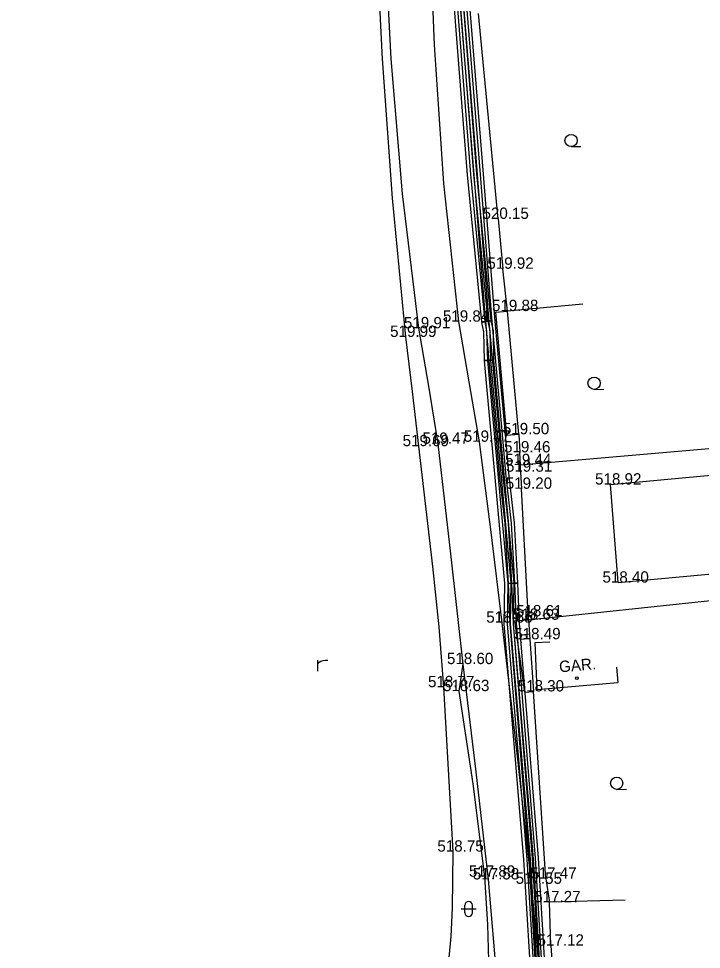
# Model space of a CAD drawing. Extents: x -669642 to -669119, y -1131006 to -1130466.
# Drawn here: x -669490.6 to -669445.4, y -1130940.6 to -1130879 of the extents above; entities that cross this region are included whole.
import ezdxf

# ---------------------------------------------------------------- set-up
doc = ezdxf.new("R2010")
doc.units = 0
for name, color, linetype in [('G_Bod_tecka', 7, 'Continuous'), ('G_Bod_vyska', 7, 'Continuous'), ('G_Breh_Teren', 7, 'Continuous'), ('G_Budovy-znacky', 7, 'Continuous'), ('G_Budovy_Objekty', 7, 'Continuous'), ('G_Plochy_zpevnene', 7, 'Continuous'), ('G_Ploty', 7, 'Continuous'), ('G_Ploty_vstupy', 7, 'Continuous'), ('G_Popisy_objektu', 7, 'Continuous'), ('G_Popisy_povrchu', 7, 'Continuous'), ('G_Site-Sloupy', 7, 'Continuous'), ('G_Z_CHRANICKA-TEPLOVOD_kotovane', 7, 'Continuous'), ('G_Z_ELsilove_podz_kotovane', 7, 'Continuous'), ('G_Z_SPOJE_podz_kotovane', 7, 'Continuous'), ('G_Zelen-Znacky', 7, 'Continuous')]:
    doc.layers.add(name, color=color, linetype=linetype)

msp = doc.modelspace()

# ---------------------------------------------------------------- linework, layer by layer
at = {"layer": 'G_Bod_tecka'}
for p, q in [((-669458.84, -1130892.24), (-669458.84, -1130892.24)), ((-669458.54, -1130895.54), (-669458.54, -1130895.54)), ((-669458.23, -1130898.34), (-669458.23, -1130898.34)), ((-669461.48, -1130899.04), (-669461.48, -1130899.04)), ((-669464.12, -1130899.48), (-669464.12, -1130899.48)), ((-669464.97, -1130900.05), (-669464.97, -1130900.05)), ((-669457.49, -1130906.49), (-669457.49, -1130906.49)), ((-669464.13, -1130907.28), (-669464.13, -1130907.28)), ((-669462.83, -1130907.12), (-669462.83, -1130907.12)), ((-669460.1, -1130906.99), (-669460.1, -1130906.99)), ((-669457.42, -1130907.69), (-669457.42, -1130907.69)), ((-669457.37, -1130908.53), (-669457.37, -1130908.53)), ((-669457.37, -1130908.97), (-669457.37, -1130908.97)), ((-669451.41, -1130909.82), (-669451.41, -1130909.82)), ((-669457.3, -1130910.1), (-669457.3, -1130910.1)), ((-669450.9, -1130916.31), (-669450.9, -1130916.31)), ((-669458.6, -1130918.96), (-669458.6, -1130918.96)), ((-669456.83, -1130918.77), (-669456.83, -1130918.77)), ((-669456.69, -1130918.54), (-669456.69, -1130918.54)), ((-669456.76, -1130920.06), (-669456.76, -1130920.06)), ((-669461.18, -1130921.7), (-669461.18, -1130921.7)), ((-669462.47, -1130923.23), (-669462.47, -1130923.23)), ((-669461.46, -1130923.49), (-669461.46, -1130923.49)), ((-669456.51, -1130923.51), (-669456.51, -1130923.51)), ((-669461.85, -1130934.11), (-669461.85, -1130934.11)), ((-669459.76, -1130935.77), (-669459.76, -1130935.77)), ((-669459.5, -1130935.95), (-669459.5, -1130935.95)), ((-669456.67, -1130936.24), (-669456.67, -1130936.24)), ((-669455.7, -1130935.9), (-669455.7, -1130935.9)), ((-669455.44, -1130937.46), (-669455.44, -1130937.46)), ((-669455.36, -1130940.33), (-669455.36, -1130940.33))]:
    msp.add_line(p, q, dxfattribs=at)
at = {"layer": 'G_Breh_Teren'}
msp.add_line((-669461.18, -1130921.7), (-669461.46, -1130923.49), dxfattribs=at)
for points in [[(-669466.84, -1130875.5), (-669466.52, -1130881.65), (-669465.86, -1130890.86), (-669464.97, -1130900.05), (-669464.55, -1130903.67), (-669464.13, -1130907.28), (-669463.19, -1130915.25), (-669462.78, -1130919.23), (-669462.47, -1130923.23), (-669462.16, -1130928.67), (-669461.85, -1130934.11)], [(-669461.46, -1130923.49), (-669460.53, -1130929.62), (-669459.76, -1130935.77), (-669459.56, -1130938.93), (-669459.43, -1130943.69), (-669459.32, -1130948.45)], [(-669461.85, -1130934.11), (-669461.9, -1130937.86), (-669461.97, -1130939.73), (-669462.15, -1130941.58), (-669462.94, -1130945.65), (-669464.57, -1130951.69), (-669466.27, -1130957.72)]]:
    msp.add_lwpolyline(points, dxfattribs=at)
at = {"layer": 'G_Budovy-znacky'}
msp.add_circle((-669453.639, -1130922.63), 0.0875, dxfattribs=at)
at = {"layer": 'G_Budovy_Objekty'}
for p, q in [((-669450.9, -1130916.31), (-669443.02, -1130915.58)), ((-669455.42, -1130920.26), (-669456.42, -1130920.3)), ((-669456.42, -1130920.3), (-669456.28, -1130923.39)), ((-669451.02, -1130921.91), (-669450.93, -1130922.91)), ((-669456.28, -1130923.39), (-669450.93, -1130922.91))]:
    msp.add_line(p, q, dxfattribs=at)
for points in [[(-669451.41, -1130909.82), (-669435.52, -1130908.33)], [(-669450.9, -1130916.31), (-669451.41, -1130909.82)]]:
    msp.add_lwpolyline(points, dxfattribs=at)
at = {"layer": 'G_Plochy_zpevnene'}
for p, q in [((-669457.77, -1130918.84), (-669456.83, -1130918.77)), ((-669457.77, -1130918.84), (-669457.11, -1130923.55)), ((-669457.11, -1130923.55), (-669456.51, -1130923.51))]:
    msp.add_line(p, q, dxfattribs=at)
for points in [[(-669463.32, -1130874.6), (-669463.08, -1130880.72), (-669462.46, -1130889.89), (-669461.48, -1130899.04), (-669460.79, -1130903.02), (-669460.1, -1130906.99), (-669459.33, -1130912.97), (-669458.6, -1130918.96), (-669457.62, -1130927.6), (-669456.67, -1130936.24), (-669456.11, -1130942.25)], [(-669466.25, -1130875.67), (-669465.96, -1130881.64), (-669465.2, -1130890.57), (-669464.12, -1130899.48), (-669463.45, -1130903.3), (-669462.83, -1130907.12), (-669462, -1130914.41), (-669461.18, -1130921.7), (-669460.33, -1130928.82), (-669459.5, -1130935.95), (-669458.98, -1130942.17)]]:
    msp.add_lwpolyline(points, dxfattribs=at)
at = {"layer": 'G_Ploty'}
for p, q in [((-669458.84, -1130892.24), (-669460.15, -1130878.65)), ((-669458.23, -1130898.34), (-669458.54, -1130895.54)), ((-669453.25, -1130897.89), (-669458.23, -1130898.34)), ((-669459.03, -1130898.41), (-669458.23, -1130898.34)), ((-669459.03, -1130898.41), (-669458.29, -1130906.56)), ((-669457.49, -1130906.49), (-669458.23, -1130898.34)), ((-669458.29, -1130906.56), (-669457.49, -1130906.49)), ((-669457.37, -1130908.53), (-669457.42, -1130907.69)), ((-669457.37, -1130908.97), (-669457.37, -1130908.53)), ((-669456.83, -1130918.77), (-669457.3, -1130910.1)), ((-669455.7, -1130935.9), (-669456.51, -1130923.51)), ((-669450.44, -1130937.32), (-669455.44, -1130937.46)), ((-669455.36, -1130940.33), (-669455.44, -1130937.46))]:
    msp.add_line(p, q, dxfattribs=at)
for points in [[(-669443.11, -1130907.31), (-669457.37, -1130908.53)], [(-669456.83, -1130918.77), (-669444.37, -1130917.45)]]:
    msp.add_lwpolyline(points, dxfattribs=at)
at = {"layer": 'G_Ploty_vstupy'}
for p, q in [((-669458.84, -1130892.24), (-669458.54, -1130895.54)), ((-669457.49, -1130906.49), (-669457.42, -1130907.69)), ((-669457.37, -1130908.97), (-669457.3, -1130910.1)), ((-669456.83, -1130918.77), (-669456.76, -1130920.06)), ((-669456.76, -1130920.06), (-669456.51, -1130923.51)), ((-669455.7, -1130935.9), (-669455.44, -1130937.46)), ((-669455.36, -1130940.33), (-669455.28, -1130941.62))]:
    msp.add_line(p, q, dxfattribs=at)
at = {"layer": 'G_Site-Sloupy'}
for radius in [0.25, 0.05]:
    msp.add_circle((-669456.69, -1130918.54), radius, dxfattribs=at)
at = {"layer": 'G_Z_CHRANICKA-TEPLOVOD_kotovane'}
for points in [[(-669463.464, -1130850.336), (-669463.211, -1130850.314), (-669462.571, -1130857.807), (-669461.451, -1130874.328), (-669460.281, -1130889.264), (-669459.334, -1130898.98), (-669459.332, -1130899.001), (-669459.63, -1130899.03), (-669459.669, -1130899.034), (-669459.929, -1130899.059), (-669460.878, -1130889.322), (-669462.049, -1130874.372), (-669463.169, -1130857.853), (-669463.809, -1130850.366)], [(-669463.088, -1130850.242), (-669462.871, -1130850.225), (-669462.091, -1130859.855), (-669461.051, -1130874.307), (-669459.841, -1130889.276), (-669459.091, -1130898.765), (-669458.411, -1130906.243), (-669458.412, -1130906.243), (-669458.462, -1130906.248), (-669458.732, -1130906.272), (-669459.009, -1130906.297), (-669459.435, -1130901.609), (-669459.435, -1130901.608), (-669459.669, -1130899.038), (-669459.669, -1130899.034), (-669459.689, -1130898.815), (-669460.439, -1130889.324), (-669461.649, -1130874.353), (-669462.689, -1130859.903), (-669463.464, -1130850.336), (-669463.469, -1130850.278), (-669463.469, -1130850.273)], [(-669459.63, -1130899.03), (-669459.337, -1130898.966), (-669459.334, -1130898.98), (-669459.187, -1130899.645), (-669459.159, -1130901.604), (-669459.159, -1130901.605), (-669459.435, -1130901.609), (-669459.453, -1130901.609), (-669459.76, -1130901.614), (-669459.787, -1130899.715), (-669459.923, -1130899.094), (-669459.669, -1130899.038)], [(-669458.412, -1130906.243), (-669458.132, -1130909.269), (-669457.781, -1130912.355), (-669457.57, -1130916.334), (-669457.81, -1130916.347), (-669457.825, -1130916.348), (-669458.17, -1130916.366), (-669458.17, -1130916.366), (-669458.379, -1130912.405), (-669458.729, -1130909.324), (-669459.009, -1130906.298), (-669458.732, -1130906.272), (-669458.462, -1130906.248)], [(-669457.81, -1130916.347), (-669457.572, -1130916.337), (-669457.461, -1130918.982), (-669456.191, -1130934.519), (-669455.313, -1130949.251), (-669453.393, -1130954.785), (-669451.504, -1130957.211), (-669448.877, -1130962.675), (-669448.87, -1130962.69), (-669449.081, -1130962.792), (-669449.14, -1130962.82), (-669449.41, -1130962.95), (-669452.016, -1130957.529), (-669453.927, -1130955.075), (-669455.907, -1130949.369), (-669456.789, -1130934.561), (-669458.059, -1130919.007), (-669458.17, -1130916.366), (-669458.17, -1130916.362), (-669457.825, -1130916.348)]]:
    msp.add_lwpolyline(points, close=True, dxfattribs=at)
msp.add_lwpolyline([(-669456.247, -1130949.405), (-669457.139, -1130934.632), (-669458.45, -1130919.06), (-669458.41, -1130916.371), (-669459.759, -1130901.637), (-669459.453, -1130901.609), (-669459.435, -1130901.608), (-669459.161, -1130901.583), (-669459.159, -1130901.604), (-669459.159, -1130901.605), (-669458.732, -1130906.272), (-669458.732, -1130906.272), (-669457.81, -1130916.347), (-669457.81, -1130916.347), (-669457.81, -1130916.349), (-669457.85, -1130919.04), (-669456.541, -1130934.588), (-669455.653, -1130949.295)], dxfattribs=at)
at = {"layer": 'G_Z_ELsilove_podz_kotovane'}
for points in [[(-669461.85, -1130874.357), (-669460.68, -1130889.299), (-669459.729, -1130899.044), (-669459.61, -1130899.661), (-669459.56, -1130901.616), (-669458.21, -1130916.364), (-669458.25, -1130919.053), (-669456.94, -1130934.617), (-669456.049, -1130949.368), (-669454.16, -1130955.298), (-669452.214, -1130957.705), (-669449.377, -1130963.09), (-669447.433, -1130966.166), (-669443.781, -1130971.308), (-669440.42, -1130975.92), (-669437.644, -1130979.538), (-669430.572, -1130986.049), (-669425.783, -1130989.308), (-669418.897, -1130995.885), (-669414.413, -1130999.608), (-669413.159, -1131000.6)], [(-669461.65, -1130874.343), (-669460.48, -1130889.281), (-669459.531, -1130899.016), (-669459.41, -1130899.639), (-669459.36, -1130901.604), (-669458.01, -1130916.356), (-669458.05, -1130919.047), (-669456.74, -1130934.603), (-669455.851, -1130949.332), (-669453.98, -1130955.202), (-669452.046, -1130957.595), (-669449.203, -1130962.99), (-669447.267, -1130966.054), (-669443.619, -1130971.192), (-669440.26, -1130975.8), (-669437.496, -1130979.402), (-669430.448, -1130985.891), (-669425.657, -1130989.152), (-669418.763, -1130995.735), (-669414.287, -1130999.452), (-669412.836, -1131000.6)]]:
    msp.add_lwpolyline(points, dxfattribs=at)
at = {"layer": 'G_Z_SPOJE_podz_kotovane'}
for points in [[(-669496.072, -1130721.41), (-669487.697, -1130721.789), (-669481.224, -1130725.264), (-669474.834, -1130730.162), (-669473.468, -1130733.802), (-669473.27, -1130736.156), (-669472.44, -1130755.333), (-669472.33, -1130769.914), (-669471.45, -1130783.056), (-669470.88, -1130792.458), (-669469.649, -1130805.302), (-669467.579, -1130819.436), (-669465.879, -1130828.666), (-669464.319, -1130839.252), (-669463.27, -1130850.259), (-669462.68, -1130857.899), (-669462.49, -1130859.888), (-669461.45, -1130874.338), (-669460.24, -1130889.308), (-669459.49, -1130898.798), (-669458.81, -1130906.279), (-669458.529, -1130909.31)], [(-669496.072, -1130721.41), (-669487.697, -1130721.789), (-669481.224, -1130725.264), (-669474.834, -1130730.162), (-669473.468, -1130733.802), (-669473.27, -1130736.156), (-669472.44, -1130755.333), (-669472.33, -1130769.914), (-669471.45, -1130783.056), (-669470.88, -1130792.458), (-669469.649, -1130805.302), (-669467.579, -1130819.436), (-669465.879, -1130828.666), (-669464.319, -1130839.252), (-669463.27, -1130850.259), (-669462.68, -1130857.899), (-669462.49, -1130859.888), (-669461.45, -1130874.338), (-669460.24, -1130889.308), (-669459.49, -1130898.798), (-669458.81, -1130906.279), (-669458.529, -1130909.31)], [(-669496.068, -1130721.21), (-669487.643, -1130721.591), (-669481.116, -1130725.096), (-669474.666, -1130730.038), (-669473.272, -1130733.758), (-669473.07, -1130736.144), (-669472.24, -1130755.327), (-669472.13, -1130769.906), (-669471.25, -1130783.044), (-669470.68, -1130792.442), (-669469.451, -1130805.278), (-669467.381, -1130819.404), (-669465.681, -1130828.634), (-669464.121, -1130839.228), (-669463.07, -1130850.241), (-669462.48, -1130857.881), (-669462.29, -1130859.872), (-669461.25, -1130874.322), (-669460.04, -1130889.292), (-669459.29, -1130898.782), (-669458.61, -1130906.261), (-669458.331, -1130909.29), (-669457.98, -1130912.372)], [(-669458.529, -1130909.31), (-669458.18, -1130912.388), (-669457.97, -1130916.355), (-669457.86, -1130919.006), (-669456.59, -1130934.547), (-669455.709, -1130949.33), (-669453.749, -1130954.978), (-669451.845, -1130957.423), (-669449.228, -1130962.868), (-669447.213, -1130966.086), (-669443.611, -1130971.139), (-669440.17, -1130975.71), (-669437.414, -1130979.337), (-669430.423, -1130985.838), (-669425.583, -1130989.138), (-669418.577, -1130995.785), (-669414.192, -1130999.479), (-669412.668, -1131000.6)], [(-669458.529, -1130909.31), (-669458.18, -1130912.388), (-669457.97, -1130916.355), (-669457.86, -1130919.006), (-669456.59, -1130934.547), (-669455.709, -1130949.33), (-669453.749, -1130954.978), (-669451.845, -1130957.423), (-669449.228, -1130962.868), (-669447.213, -1130966.086), (-669443.611, -1130971.139), (-669440.17, -1130975.71), (-669437.414, -1130979.337), (-669430.423, -1130985.838), (-669425.583, -1130989.138), (-669418.577, -1130995.785), (-669414.192, -1130999.479), (-669412.668, -1131000.6)], [(-669457.98, -1130912.372), (-669457.77, -1130916.345), (-669457.66, -1130918.994), (-669456.39, -1130934.533), (-669455.511, -1130949.29), (-669453.571, -1130954.882), (-669451.675, -1130957.317), (-669449.052, -1130962.772), (-669447.047, -1130965.974), (-669443.449, -1130971.021), (-669440.01, -1130975.59), (-669437.266, -1130979.203), (-669430.297, -1130985.682), (-669425.457, -1130988.982), (-669418.443, -1130995.635), (-669414.068, -1130999.321), (-669412.329, -1131000.6)]]:
    msp.add_lwpolyline(points, dxfattribs=at)
at = {"layer": 'G_Zelen-Znacky'}
for p, q in [((-669452.502, -1130903.52), (-669451.852, -1130903.517)), ((-669470.79, -1130922.171), (-669470.79, -1130921.439))]:
    msp.add_line(p, q, dxfattribs=at)
for points in [[(-669454.022, -1130887.45), (-669453.372, -1130887.447)], [(-669470.79, -1130921.675), (-669470.688, -1130921.58), (-669470.585, -1130921.517), (-669470.428, -1130921.47), (-669470.278, -1130921.447), (-669470.121, -1130921.439)], [(-669451.002, -1130929.99), (-669450.352, -1130929.987)], [(-669460.3, -1130937.91), (-669461.3, -1130937.91)], [(-669461.05, -1130938.16), (-669461.05, -1130937.66)], [(-669460.55, -1130938.16), (-669460.55, -1130937.66)]]:
    msp.add_lwpolyline(points, dxfattribs=at)
for centre in [(-669454.022, -1130887.047), (-669452.502, -1130903.117), (-669451.002, -1130929.587)]:
    msp.add_circle(centre, 0.403, dxfattribs=at)
for centre, start, end in [((-669460.801, -1130937.659), 0, 180), ((-669460.801, -1130938.159), 180, 0)]:
    msp.add_arc(centre, 0.25, start, end, dxfattribs=at)

# ---------------------------------------------------------------- texts
at = {"layer": 'G_Bod_vyska'}
for s, p in [('520.15', (-669459.884, -1130892.24)), ('519.92', (-669459.564, -1130895.54)), ('519.88', (-669459.254, -1130898.34)), ('519.91', (-669465.084, -1130899.48)), ('519.84', (-669462.504, -1130899.04)), ('519.99', (-669465.998, -1130900.05)), ('519.50', (-669458.536, -1130906.49)), ('519.69', (-669465.17, -1130907.28)), ('519.47', (-669463.854, -1130907.12)), ('519.47', (-669461.124, -1130906.99)), ('519.46', (-669458.458, -1130907.69)), ('519.44', (-669458.394, -1130908.53)), ('519.31', (-669458.333, -1130908.97)), ('518.92', (-669452.434, -1130909.82)), ('519.20', (-669458.346, -1130910.1)), ('518.40', (-669451.944, -1130916.31)), ('518.61', (-669457.664, -1130918.54)), ('518.65', (-669459.636, -1130918.96)), ('518.63', (-669457.866, -1130918.77)), ('518.49', (-669457.784, -1130920.06)), ('518.60', (-669462.238, -1130921.7)), ('518.77', (-669463.492, -1130923.23)), ('518.63', (-669462.496, -1130923.49)), ('518.30', (-669457.554, -1130923.51)), ('518.75', (-669462.872, -1130934.11)), ('517.89', (-669460.784, -1130935.77)), ('517.47', (-669456.722, -1130935.9)), ('517.58', (-669460.522, -1130935.95)), ('517.55', (-669457.692, -1130936.24)), ('517.27', (-669456.462, -1130937.46)), ('517.12', (-669456.241, -1130940.33))]:
    msp.add_text(s, height=0.75, dxfattribs=at).set_placement(p)
at = {"layer": 'G_Popisy_objektu'}
msp.add_text('GAR.', height=0.75, rotation=5.12683, dxfattribs=at).set_placement((-669454.782, -1130922.253))
at = {"layer": 'G_Popisy_povrchu'}
msp.add_text('b.', height=0.6, rotation=277.99225, dxfattribs=at).set_placement((-669457.451, -1130919.713))

doc.saveas('drawing.dxf')
